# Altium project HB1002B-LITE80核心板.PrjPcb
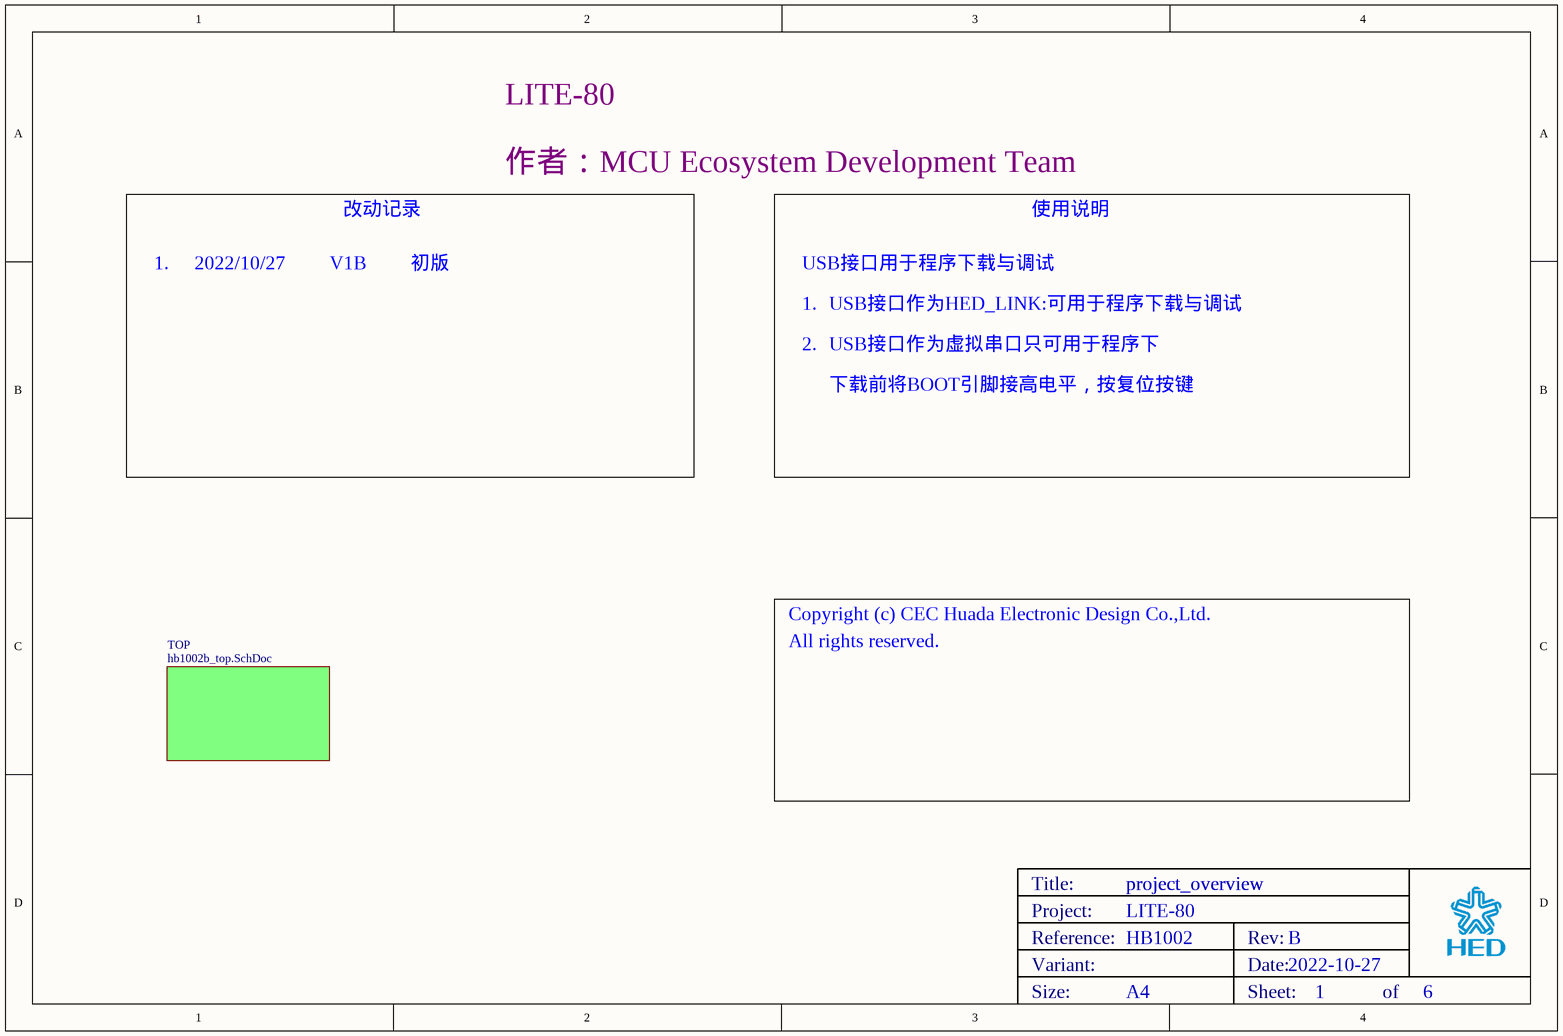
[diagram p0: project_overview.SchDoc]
Board_Assembly_Revision: 01; Board_Name: LITE-80; Board_PCB_Revision: B; Board_Reference: HB1002
6 sheets, 120 parts. Net scope: global (net labels, ports and power ports of the same name join across sheets).
Board file: hb1002b.PcbDoc
Sheets:
  project_overview.SchDoc
    TOP = hb1002b_top.SchDoc
      hed_link = hed_link.SchDoc
      arduino_extension_interfaces = arduino_extension_interfaces.SchDoc
      MCU = mcu.SchDoc
      power = power.SchDoc

## Sheet project_overview.SchDoc: project_overview
size A4; Date: 2022-10-27; DrawnBy: liuchao; SheetNumber: 1; SheetTotal: 6

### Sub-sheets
TOP = hb1002b_top.SchDoc: no entries

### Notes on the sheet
- 作者：MCU Ecosystem Development Team
- 改动记录
- 使用说明
- 1.
- 2022/10/27
- V1B
- 初版
- USB接口用于程序下载与调试
- USB接口作为HED_LINK:可用于程序下载与调试
- 2.
- USB接口作为虚拟串口只可用于程序下
- 下载前将BOOT引脚接高电平，按复位按键
- Copyright (c) CEC Huada Electronic Design Co.,Ltd.
- All rights reserved.

## Sheet hb1002b_top.SchDoc: top
size A4; Date: 2022-10-27; DrawnBy: liuchao; SheetNumber: 2; SheetTotal: 6
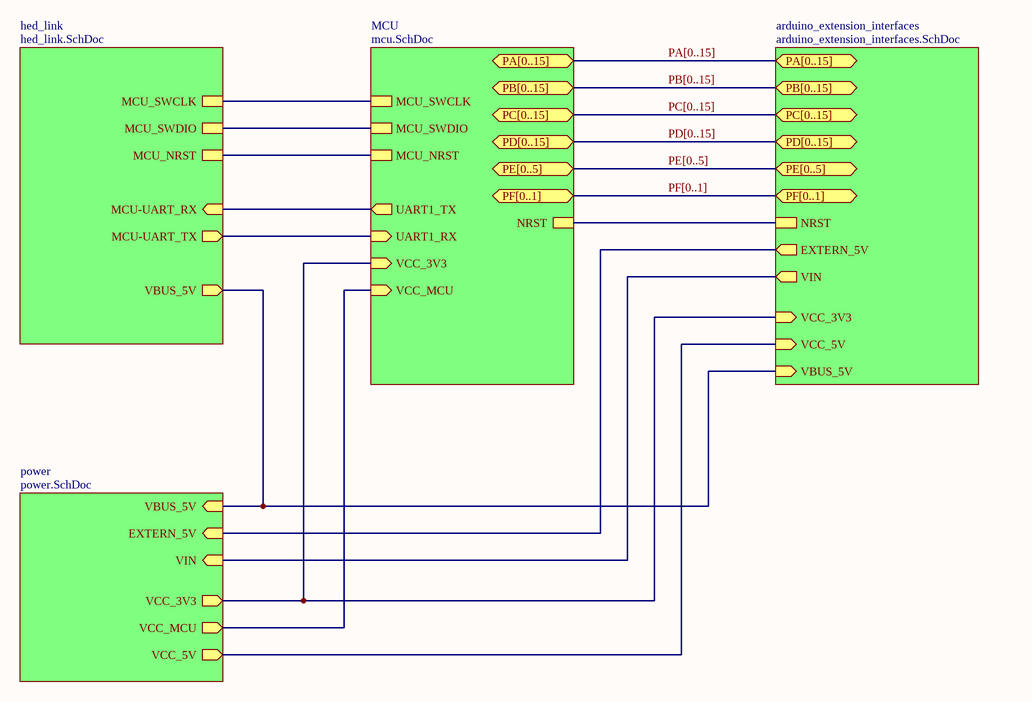
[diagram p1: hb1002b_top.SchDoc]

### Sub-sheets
arduino_extension_interfaces = arduino_extension_interfaces.SchDoc: NRST, VBUS_5V (in), EXTERN_5V (out), VIN (out), VCC_3V3 (in), VCC_5V (in)
hed_link = hed_link.SchDoc: MCU_SWDIO, MCU_SWCLK, MCU_NRST, MCU-UART_RX (in), MCU-UART_TX (out), VBUS_5V (out)
MCU = mcu.SchDoc: UART1_RX (in), UART1_TX (out), MCU_SWCLK, MCU_SWDIO, MCU_NRST, VCC_3V3 (in), VCC_MCU (in), NRST
power = power.SchDoc: VCC_MCU (out), VBUS_5V (in), EXTERN_5V (in), VIN (in), VCC_3V3 (out), VCC_5V (out)

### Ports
PA[0..15], PB[0..15], PC[0..15], PD[0..15], PE[0..5], PF[0..1]

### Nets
(unnamed): sheet hed_link/MCU_SWDIO, sheet MCU/MCU_SWDIO
(unnamed): sheet hed_link/MCU_SWCLK, sheet MCU/MCU_SWCLK  [a separate net that carries the same name]
(unnamed): sheet hed_link/MCU_NRST, sheet MCU/MCU_NRST  [a separate net that carries the same name]
(unnamed): sheet hed_link/MCU-UART_RX, sheet MCU/UART1_TX  [a separate net that carries the same name]
(unnamed): sheet hed_link/MCU-UART_TX, sheet MCU/UART1_RX  [a separate net that carries the same name]
(unnamed): sheet hed_link/VBUS_5V, sheet arduino_extension_interfaces/VBUS_5V, sheet power/VBUS_5V  [a separate net that carries the same name]
(unnamed): sheet arduino_extension_interfaces/NRST, sheet MCU/NRST  [a separate net that carries the same name]
(unnamed): sheet arduino_extension_interfaces/EXTERN_5V, sheet power/EXTERN_5V  [a separate net that carries the same name]
(unnamed): sheet arduino_extension_interfaces/VIN, sheet power/VIN  [a separate net that carries the same name]
(unnamed): sheet arduino_extension_interfaces/VCC_3V3, sheet MCU/VCC_3V3, sheet power/VCC_3V3  [a separate net that carries the same name]
(unnamed): sheet arduino_extension_interfaces/VCC_5V, sheet power/VCC_5V  [a separate net that carries the same name]
(unnamed): sheet MCU/VCC_MCU, sheet power/VCC_MCU  [a separate net that carries the same name]

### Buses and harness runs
bus PA[0..15] = port PA[0..15]
bus PB[0..15] = port PB[0..15]
bus PC[0..15] = port PC[0..15]
bus PD[0..15] = port PD[0..15]
bus PE[0..5] = port PE[0..5]
bus PF[0..1] = port PF[0..1]

## Sheet hed_link.SchDoc: HED_Link
size A4; Date: 2022-10-27; DrawnBy: liuchao; SheetNumber: 6; SheetTotal: 6
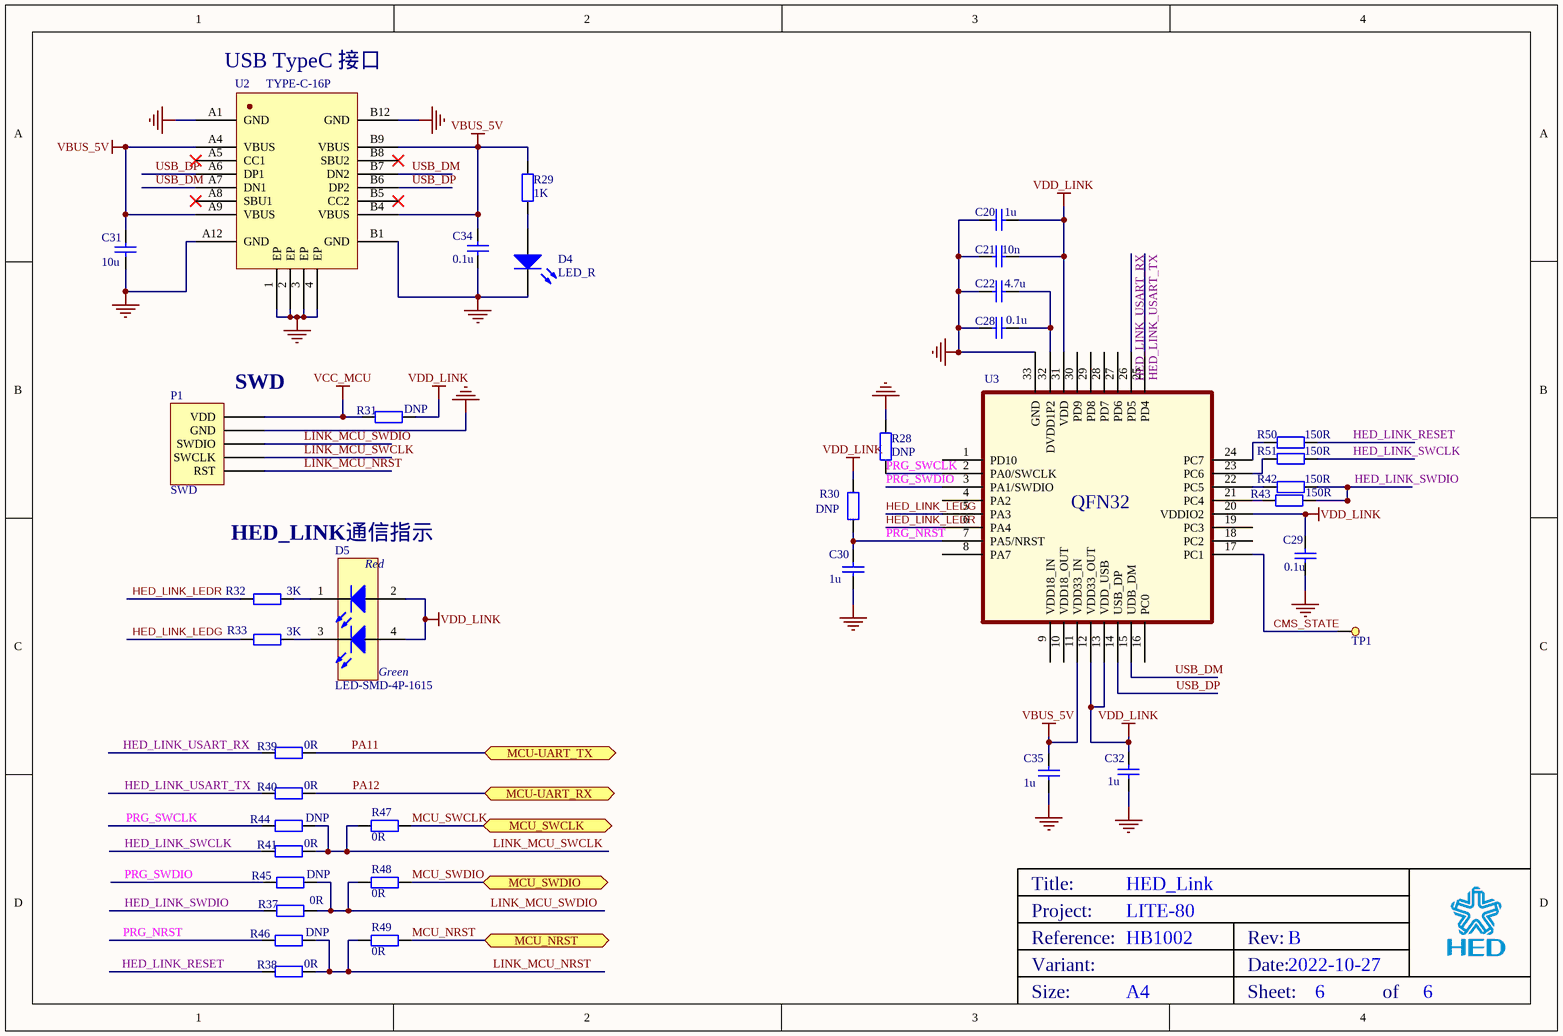
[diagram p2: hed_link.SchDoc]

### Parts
C20  1u  [0603]
C21  10n  [0603]
C22  4.7u  [0603]
C28  0.1u  [0603]
C29  0.1u  [0603]
C30  value 1u  [0603]  (hidden comment: 0.1u)
C31  10u  [0603]
C32  1u  [0603]
C34  0.1u  [0603]
C35  1u  [0603]
D4  LED_R  [0603 - p]
D5  Manufacturer_Part_Number: LED-SMD-4P-1615  [LED-SMD_4P_1615]  (hidden comment: LD_BICOLOR_CMS)
P1  SWD  [HED_5_4_2.5]
R28  DNP  [0603]
R29  1K  [0603]
R30  DNP  [0603]
R31  DNP  [0603]
R32  3K  [0603]
R33  3K  [0603]
R37  0R  [0603]
R38  0R  [0603]
R39  0R  [0603]
R40  0R  [0603]
R41  0R  [0603]
R42  150R  [0603]
R43  150R  [0603]
R44  DNP  [0603]
R45  DNP  [0603]
R46  DNP  [0603]
R47  0R  [0603]
R48  0R  [0603]
R49  0R  [0603]
R50  150R  [0603]
R51  150R  [0603]
TP1  TEST_POINT  [TEST_POINT]  (value not drawn)
U2  TYPE-C-16P  [HED-KH-TYPE-C-16P]
U3  MCU  [HED-QFN-32_5x5x05P]  (value not drawn)

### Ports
MCU-UART_RX (bidir), MCU-UART_TX (bidir), MCU_NRST, MCU_SWCLK, MCU_SWDIO

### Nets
GND: C20.1 C21.1 C22.1 C28.1 C29.2 C30.2 C31.1 C32.2 C34.1 C35.2 D4.2(K) P1.2(GND) R28.1 U2.1(EP) U2.2(EP) U2.3(EP) U2.4(EP) U2.A1(GND) U2.A12(GND) U2.B1(GND) U2.B12(GND) U3.33(GND)
VBUS_5V: C31.2 C34.2 C35.1 R29.1 U2.A4(VBUS) U2.A9(VBUS) U2.B4(VBUS) U2.B9(VBUS) U3.11(VDD33_IN)
VCC_MCU: P1.1(VDD) R31.1
VDD_LINK: C20.2 C21.2 C29.1 C32.1 D5.2(RED_cathode) D5.4(YellowGreen_anode) R30.1 R31.2 U3.12(VDD33_OUT) U3.13(VDD_USB) U3.20(VDDIO2) U3.31(VDD)
CMS_STATE: TP1.1 U3.17(PC1)
HED_LINK_LEDG: R33.1 U3.5(PA3)
HED_LINK_LEDR: R32.1 U3.6(PA4)
HED_LINK_RESET: R38.1 R50.2
HED_LINK_SWCLK: R41.1 R51.2
HED_LINK_SWDIO: R37.1 R42.2 R43.2
HED_LINK_USART_RX: R39.1 U3.26(PD5)
HED_LINK_USART_TX: R40.1 U3.25(PD4)
LINK_MCU_NRST: P1.5(RST) R38.2 R46.2 R49.2
LINK_MCU_SWCLK: P1.4(SWCLK) R41.2 R44.2 R47.2
LINK_MCU_SWDIO: P1.3(SWDIO) R37.2 R45.2 R48.2
MCU_NRST: R49.1 ; port MCU_NRST
MCU_SWCLK: R47.1 ; port MCU_SWCLK
MCU_SWDIO: R48.1 ; port MCU_SWDIO
PA11: R39.2 ; port MCU-UART_TX
PA12: R40.2 ; port MCU-UART_RX
PRG_NRST: C30.1 R30.2 R46.1 U3.7(PA5/NRST)
PRG_SWCLK: R28.2 R44.1 U3.2(PA0/SWCLK)
PRG_SWDIO: R45.1 U3.3(PA1/SWDIO)
USB_DM: U2.A7(DN1) U2.B7(DN2) U3.15(UDB_DM)
USB_DP: U2.A6(DP1) U2.B6(DP2) U3.14(USB_DP)
NetC22_2: C22.2 C28.2 U3.32(DVDD1P2)
NetD4_1: D4.1(A) R29.2
NetD5_1: D5.1(Red_anode) R32.2
NetD5_3: D5.3(YellowGreen_cathode) R33.2
NetR42_1: R42.1 U3.22(PC5)
NetR43_1: R43.1 U3.21(PC4)
NetR50_1: R50.1 U3.24(PC7)
NetR51_1: R51.1 U3.23(PC6)

Not connected (* = marked no-connect by the designer): U2 A5(CC1)* A8(SBU1)* B5(CC2)* B8(SBU2)*; U3 1(PD10) 4(PA2) 8(PA7) 9(VDD18_IN) 10(VDD18_OUT) 16(PC0) 18(PC2) 19(PC3) 27(PD6) 28(PD7) 29(PD8) 30(PD9)

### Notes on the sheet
- (near U2) USB TypeC 接口
- (near P1) SWD
- HED_LINK通信指示

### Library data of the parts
C20-C22 C28-C30 C32 C35 = MCD-00211: Capacitor, MLCC, 100nF, 16V, X7R, 10%, 0603, T=0,8mm; Manufacturer_Part_Number: CC0603KRX7R7BB104; Manufacturer: YAGEO; Provided_By: Subcon; Initial_Board_Reference: mb1319
C31 = 0603 4.7uF 10% 16V: 贴片电容
C34 = 0603 100nF 10% 50V: 贴片电容
D4 = LED3: Typical BLUE SiC LED; sold/unsold: sold
D5 = LD_BICOLOR_CMS: LED Bicolor; Internal_Part_Number: MCD-00051; Part_Type: Display; Manufacturer: AVAGO TECHNOLOGIES; Alternate_Manufacturer_Part_Number: LE-RGW35280; Alternate_Manufacturer: EVERLUCK; ECCN_US: EAR99; ECCN_EU: NEC; Provided_By: Subcon; Initial_Board_Reference: mb1274
R28 R42-R51 = Res: 贴片电阻; Value: 1K
R29 = Res2: 贴片电阻
R30-R33 R37-R41 = Res2: 贴片电阻; Value: 1K
U2 = KH-TYPE-C-16P: TYPE-C USB接口
U3 = CIU98-H

## Sheet arduino_extension_interfaces.SchDoc: arduino interface
size A4; Date: 2022-10-27; DrawnBy: liuchao; SheetNumber: 5; SheetTotal: 6
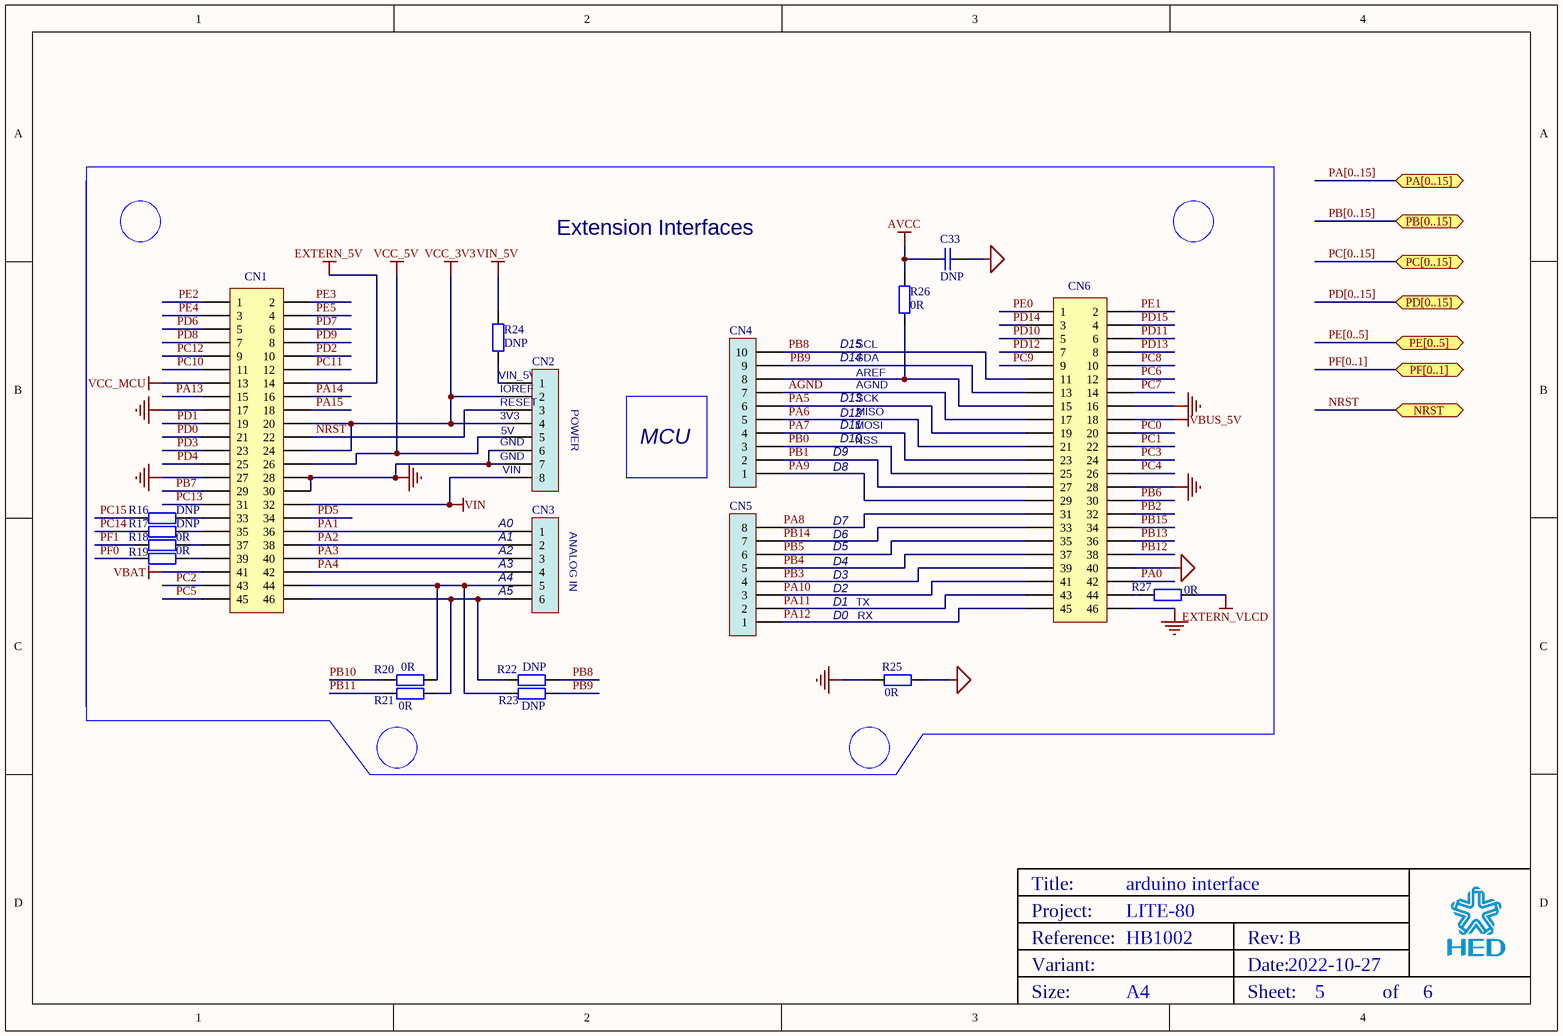
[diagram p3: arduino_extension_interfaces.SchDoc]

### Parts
C33  DNP  [0603]
CN1  Header 23x2  [HEADER_1X23_2.54]  (value not drawn)
CN2  Socket 8x1  [HEADER_1X8_2.54]  (value not drawn)
CN3  Socket 6x1  [HEADER_1X6-2.54]  (value not drawn)
CN4  Socket 10x1  [HEADER_1X10_2.54]  (value not drawn)
CN5  Socket 8x1  [HEADER_1X8_2.54]  (value not drawn)
CN6  Header 23x2  [HEADER_1X23_2.54]  (value not drawn)
R16  DNP  [0603]
R17  DNP  [0603]
R18  0R  [0603]
R19  0R  [0603]
R20  0R  [0603]
R21  0R  [0603]
R22  DNP  [0603]
R23  DNP  [0603]
R24  DNP  [0603]
R25  0R  [0603]
R26  0R  [0603]
R27  0R  [0603]

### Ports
NRST, PA[0..15] (bidir), PB[0..15] (bidir), PC[0..15] (bidir), PD[0..15], PE[0..5], PF[0..1] (bidir)

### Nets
AGND: C33.1 CN4.7 CN6.17 CN6.40 R25.1
EXTERN_5V: CN1.14
EXTERN_VLCD: R27.1
GND: CN1.17 CN1.27 CN1.28 CN1.30 CN2.6 CN2.7 CN6.16 CN6.28 CN6.46 R25.2
PA0: C33.2 CN6.42 R26.1  [also labelled AVCC]
VBAT: CN1.41
VBUS_5V: CN6.18
VCC_3V3: CN1.20 CN1.24 CN2.2 CN2.4
VCC_5V: CN1.26 CN2.5
VCC_MCU: CN1.13
VIN: CN1.32 CN2.8
VIN_5V: R24.1
NRST: CN1.22 CN2.3 ; port NRST
PA1: CN1.36 CN3.1
PA2: CN1.38 CN3.2
PA3: CN1.40 CN3.3
PA4: CN1.42 CN3.4
PA5: CN4.6 CN6.19
PA6: CN4.5 CN6.21
PA7: CN4.4 CN6.23
PA8: CN5.8 CN6.31
PA9: CN4.1 CN6.29
PA10: CN5.3 CN6.41
PA11: CN5.2 CN6.43
PA12: CN5.1 CN6.45
PA13: CN1.15
PA14: CN1.16
PA15: CN1.18
PB0: CN4.3 CN6.25
PB1: CN4.2 CN6.27
PB2: CN6.32
PB3: CN5.4 CN6.39
PB4: CN5.5 CN6.37
PB5: CN5.6 CN6.35
PB6: CN6.30
PB7: CN1.29
PB8: CN4.10 CN6.11 R22.1
PB9: CN4.9 CN6.13 R23.1
PB10: R20.2
PB11: R21.2
PB12: CN6.38
PB13: CN6.36
PB14: CN5.7 CN6.33
PB15: CN6.34
PC0: CN6.20
PC1: CN6.22
PC2: CN1.43
PC3: CN6.24
PC4: CN6.26
PC5: CN1.45
PC6: CN6.12
PC7: CN6.14
PC8: CN6.10
PC9: CN6.9
PC10: CN1.11
PC11: CN1.12
PC12: CN1.9
PC13: CN1.31
PC14: R17.2
PC15: R16.2
PD0: CN1.21
PD1: CN1.19
PD2: CN1.10
PD3: CN1.23
PD4: CN1.25
PD5: CN1.34
PD6: CN1.5
PD7: CN1.6
PD8: CN1.7
PD9: CN1.8
PD10: CN6.5
PD11: CN6.6
PD12: CN6.7
PD13: CN6.8
PD14: CN6.3
PD15: CN6.4
PE0: CN6.1
PE1: CN6.2
PE2: CN1.1
PE3: CN1.2
PE4: CN1.3
PE5: CN1.4
PF0: R19.2
PF1: R18.2
NetCN1_33: CN1.33 R16.1
NetCN1_35: CN1.35 R17.1
NetCN1_37: CN1.37 R18.1
NetCN1_39: CN1.39 R19.1
NetCN1_44: CN1.44 CN3.5 R20.1 R23.2
NetCN1_46: CN1.46 CN3.6 R21.1 R22.2
NetCN2_1: CN2.1 R24.2
NetCN4_8: CN4.8 CN6.15 R26.2
NetCN6_44: CN6.44 R27.2

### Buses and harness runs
bus PA[0..15] = port PA[0..15]
bus PB[0..15] = port PB[0..15]
bus PC[0..15] = port PC[0..15]
bus PD[0..15] = port PD[0..15]
bus PE[0..5] = port PE[0..5]
bus PF[0..1] = port PF[0..1]

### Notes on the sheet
- Extension Interfaces
- (near CN2) VIN_5V
- D14
- D15
- (near R26) SDA
- (near R26) SCL
- AREF
- (near CN2) IOREF
- (near CN2) 3V3
- (near CN2) GND
- (near CN2) RESET
- (near CN2) 5V
- (near CN2) POWER
- MCU
- D10
- D13
- D12
- D11
- MOSI
- NSS
- AGND
- MISO
- SCK
- (near CN2) VIN
- D8
- D9
- (near CN3) A0
- (near CN3) A1
- (near CN3) A2
- (near CN3) A3
- (near CN3) A4
- (near CN3) ANALOG IN
- D4
- D3
- D5
- D6
- D7
- (near CN3) A5
- D0
- D1
- D2
- TX
- RX

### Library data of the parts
C33 = MCD-00211: as C20 on sheet hed_link
CN1 CN6 = Header 23x2: Header, 19x2, 2,54mm, VR, TH, Height 5.84mm/10.16mm; Internal_Part_Number: MCD-00213; Manufacturer: SAMTEC; Part_Type: Connector; Manufacturer_Part_Number: TSW-119-09-x-D1; Value: Header 19x2; Provided_By: Subcon; Initial_Board_Reference: mb1319
CN2 = MCD-00261: Socket, 8x1, 2.54mm, VR, TH, Height 8.51mm/10mm; Manufacturer_Part_Number: SSW-108-03-x-S; Manufacturer: SAMTEC; Part_Type: Connector; Provided_By: Subcon; Initial_Board_Reference: mb1319
CN3 = MCD-00260: Socket, 6x1, 2.54mm, VR, TH, Height 8.51mm/10mm; Part_Type: Connector; Manufacturer_Part_Number: SSW-106-03-x-S; Manufacturer: SAMTEC; Provided_By: Subcon; Initial_Board_Reference: mb1319
CN4 = MCD-00262: Socket, 10x1, 2.54mm, VR, TH, Height 8.51mm/10mm; Manufacturer_Part_Number: SSW-110-03-x-S; Manufacturer: SAMTEC; Part_Type: Connector; Provided_By: Subcon; Initial_Board_Reference: mb1319
CN5 = MCD-00261: Socket, 8x1, 2.54mm, VR, TH, Height 8.51mm/10mm; Part_Type: Connector; Manufacturer_Part_Number: SSW-108-03-x-S; Manufacturer: SAMTEC; Provided_By: Subcon; Initial_Board_Reference: mb1319
R16-R27 = Res2: 贴片电阻; Value: 1K

## Sheet mcu.SchDoc: MCU
size A4; Date: 2022-10-27; DrawnBy: liuchao; SheetNumber: 3; SheetTotal: 6
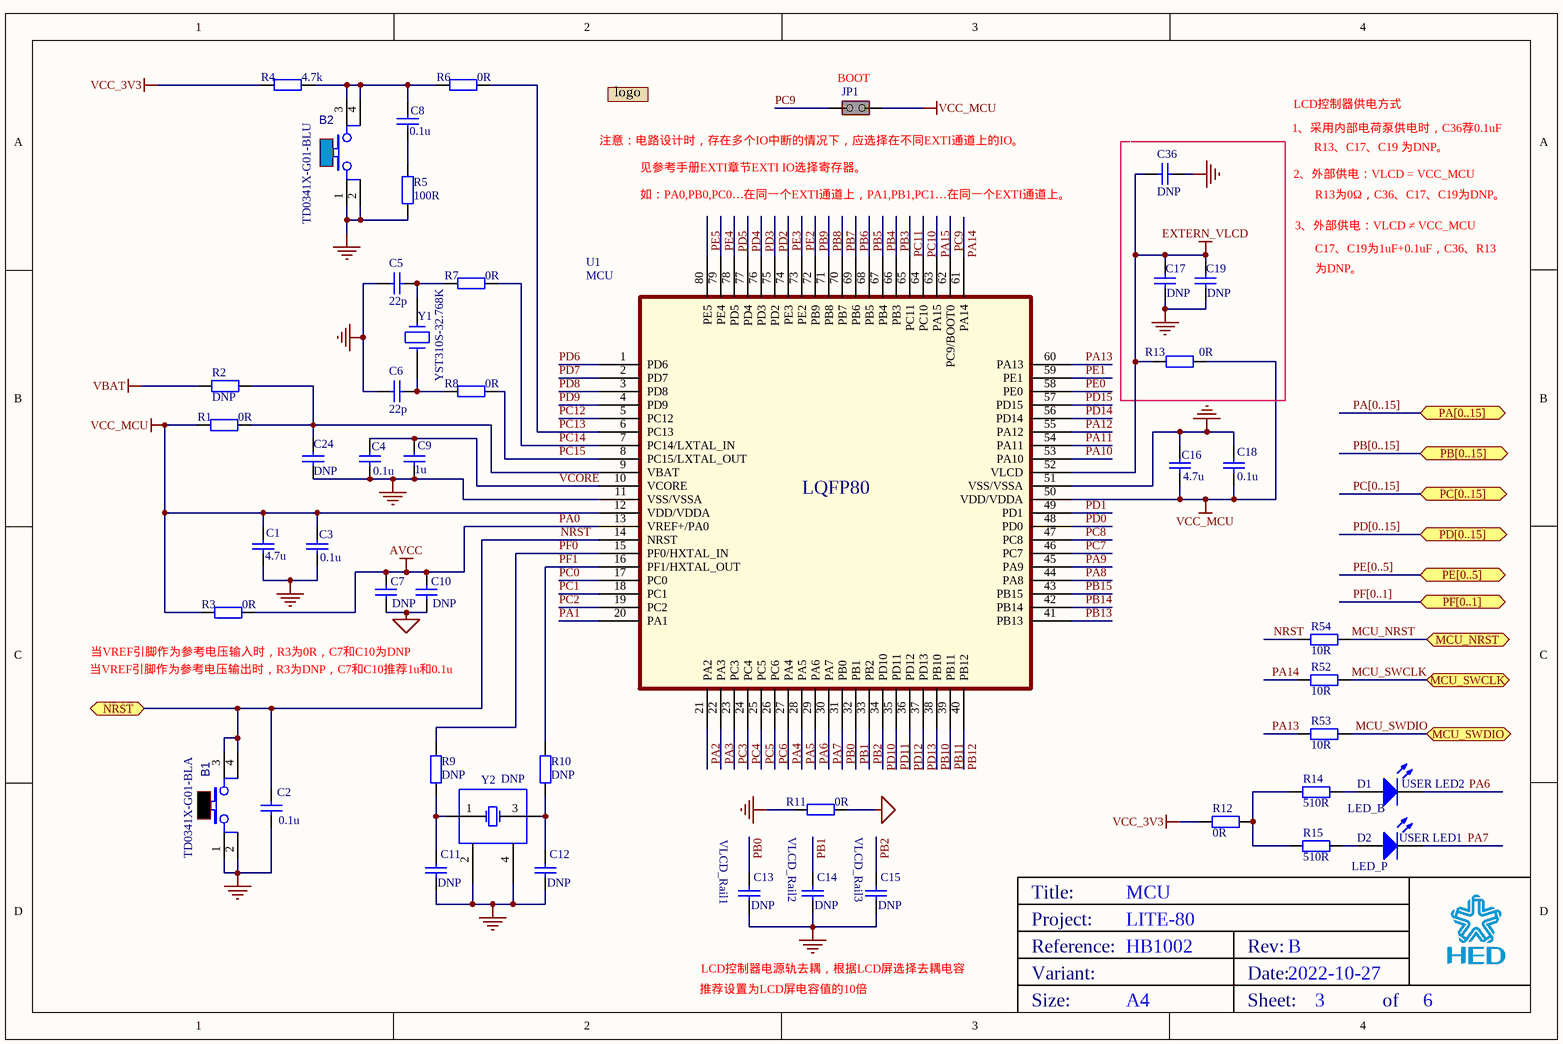
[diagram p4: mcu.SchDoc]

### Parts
B1  Manufacturer_Part_Number: TD0341X-G01-BLA  [SWI_WEALTHMETAL_TD-0341_4P_BLACK]  (hidden comment: SW-PUSH-CMS_BLACK)
B2  Manufacturer_Part_Number: TD0341X-G01-BLU  [SWI_WEALTHMETAL_TD-0341_4P_BLUE]  (hidden comment: SW-PUSH-CMS_BLUE)
C1  4.7u  [0603]
C2  0.1u  [0603]
C3  0.1u  [0603]
C4  0.1u  [0603]
C5  22p  [0603]
C6  22p  [0603]
C7  DNP  [0603]
C8  0.1u  [0603]
C9  1u  [0603]
C10  DNP  [0603]
C11  DNP  [0603]
C12  DNP  [0603]
C13  DNP  [0603]
C14  DNP  [0603]
C15  DNP  [0603]
C16  4.7u  [0603]
C17  DNP  [0603]
C18  0.1u  [0603]
C19  DNP  [0603]
C24  DNP  [0603]
C36  DNP  [0603]
D1  LED_B  [0603 - p]
D2  LED_P  [0603 - p]
JP1  Shunt Fitted  [HEADER_1X2_2.54]  (value not drawn)
logo1  logo  [华大电子LOGO]  (value not drawn)
R1  0R  [0603]
R2  DNP  [0603]
R3  0R  [0603]
R4  4.7k  [0603]
R5  100R  [0603]
R6  0R  [0603]
R7  0R  [0603]
R8  0R  [0603]
R9  DNP  [0603]
R10  DNP  [0603]
R11  0R  [0603]
R12  0R  [0603]
R13  0R  [0603]
R14  510R  [0603]
R15  510R  [0603]
R52  10R  [0603]
R53  10R  [0603]
R54  10R  [0603]
U1  MCU  [LQFP-80N-12X12]
Y1  value YST310S-32.768K  [CRY_3215SA_2P]  (hidden comment: YST310S)
Y2  DNP  [3.2*2.5*0.7 OSC]

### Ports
MCU_NRST, MCU_SWCLK, MCU_SWDIO, NRST, PA[0..15] (bidir), PB[0..15] (bidir), PC[0..15] (bidir), PD[0..15], PE[0..5], PF[0..1] (bidir)

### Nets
AGND: C7.1 C10.1 R11.1
EXTERN_VLCD: C17.1 C19.1 C36.1 R13.1 U1.52(VLCD)
GND: B1.1 B1.2 B2.1 B2.2 C1.1 C2.2 C3.1 C4.2 C5.1 C6.1 C9.2 C11.2 C12.2 C13.2 C14.2 C15.2 C16.2 C17.2 C18.2 C19.2 C24.1 C36.2 R5.2 R11.2 U1.11(VSS/VSSA) U1.51(VSS/VSSA) Y2.2(OSC2) Y2.4(OSC4)
PA0: C7.2 C10.2 R3.1 U1.13(VREF+/PA0)  [also labelled AVCC]
VBAT: R2.1
VCC_3V3: R4.2 R12.2
VCC_MCU: C1.2 C3.2 C16.1 C18.1 JP1.2(NO) R1.2 R3.2 R13.2 U1.12(VDD/VDDA) U1.50(VDD/VDDA)
MCU_NRST: R54.1 ; port MCU_NRST
MCU_SWCLK: R52.1 ; port MCU_SWCLK
MCU_SWDIO: R53.1 ; port MCU_SWDIO
NRST: B1.3 B1.4 C2.1 R54.2 U1.14(NRST) ; port NRST
PA1: U1.20(PA1)
PA2: U1.21(PA2)
PA3: U1.22(PA3)
PA4: U1.27(PA4)
PA5: U1.28(PA5)
PA6: D1.2(K) U1.29(PA6)
PA7: D2.2(K) U1.30(PA7)
PA8: U1.44(PA8)
PA9: U1.45(PA9)
PA10: U1.53(PA10)
PA11: U1.54(PA11)
PA12: U1.55(PA12)
PA13: R53.2 U1.60(PA13)
PA14: R52.2 U1.61(PA14)
PA15: U1.63(PA15)
PB0: C13.1 U1.31(PB0)
PB1: C14.1 U1.32(PB1)
PB2: C15.1 U1.33(PB2)
PB3: U1.66(PB3)
PB4: U1.67(PB4)
PB5: U1.68(PB5)
PB6: U1.69(PB6)
PB7: U1.70(PB7)
PB8: U1.71(PB8)
PB9: U1.72(PB9)
PB10: U1.38(PB10)
PB11: U1.39(PB11)
PB12: U1.40(PB12)
PB13: U1.41(PB13)
PB14: U1.42(PB14)
PB15: U1.43(PB15)
PC0: U1.17(PC0)
PC1: U1.18(PC1)
PC2: U1.19(PC2)
PC3: U1.23(PC3)
PC4: U1.24(PC4)
PC5: U1.25(PC5)
PC6: U1.26(PC6)
PC7: U1.46(PC7)
PC8: U1.47(PC8)
PC9: JP1.1(COMMON) U1.62(PC9/BOOT0)
PC10: U1.64(PC10)
PC11: U1.65(PC11)
PC12: U1.5(PC12)
PC13: R6.1 U1.6(PC13)
PC14: R7.1 U1.7(PC14/LXTAL_IN)
PC15: R8.1 U1.8(PC15/LXTAL_OUT)
PD0: U1.48(PD0)
PD1: U1.49(PD1)
PD2: U1.75(PD2)
PD3: U1.76(PD3)
PD4: U1.77(PD4)
PD5: U1.78(PD5)
PD6: U1.1(PD6)
PD7: U1.2(PD7)
PD8: U1.3(PD8)
PD9: U1.4(PD9)
PD10: U1.34(PD10)
PD11: U1.35(PD11)
PD12: U1.36(PD12)
PD13: U1.37(PD13)
PD14: U1.56(PD14)
PD15: U1.57(PD15)
PE0: U1.58(PE0)
PE1: U1.59(PE1)
PE2: U1.73(PE2)
PE3: U1.74(PE3)
PE4: U1.79(PE4)
PE5: U1.80(PE5)
PF0: R9.2 U1.15(PF0/HXTAL_IN)
PF1: R10.2 U1.16(PF1/HXTAL_OUT)
VCORE: C4.1 C9.1 U1.10(VCORE)
NetB2_3: B2.3 B2.4 C8.2 R4.1 R6.2
NetC5_2: C5.2 R7.2 Y1.1
NetC6_2: C6.2 R8.2 Y1.2
NetC8_1: C8.1 R5.1
NetC11_1: C11.1 R9.1 Y2.1(OSC1)
NetC12_1: C12.1 R10.1 Y2.3(OSC3)
NetC24_2: C24.2 R1.1 R2.2 U1.9(VBAT)
NetD1_1: D1.1(A) R14.1
NetD2_1: D2.1(A) R15.1
NetR12_1: R12.1 R14.2 R15.2

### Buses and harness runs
bus PA[0..15] = port PA[0..15]
bus PB[0..15] = port PB[0..15]
bus PC[0..15] = port PC[0..15]
bus PD[0..15] = port PD[0..15]
bus PE[0..5] = port PE[0..5]
bus PF[0..1] = port PF[0..1]

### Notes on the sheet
- (near JP1) BOOT
- LCD控制器供电方式
- 注意：电路设计时，存在多个IO中断的情况下，应选择在不同EXTI通道上的IO。
- 见参考手册EXTI章节EXTI IO选择寄存器。
- 1、采用内部电荷泵供电时，C36荐0.1uF
- 2、外部供电：VLCD = VCC_MCU
- R13、C17、C19 为DNP。
- 如：PA0,PB0,PC0…在同一个EXTI通道上，PA1,PB1,PC1…在同一个EXTI通道上。
- 3、外部供电：VLCD ≠ VCC_MCU
- C17、C19为1uF+0.1uF，C36、R13
- R13为0Ω，C36、C17、C19为DNP。
- 为DNP。
- (near R3) 当VREF引脚作为参考电压输入时，R3为0R，C7和C10为DNP
- (near R3) 当VREF引脚作为参考电压输出时，R3为DNP，C7和C10推荐1u和0.1u
- (near D1) USER LED2
- (near C13) VLCD_Rail1
- (near C14) VLCD_Rail2
- (near C15) VLCD_Rail3
- (near D2) USER LED1
- 推荐设置为LCD屏电容值的10倍
- LCD控制器电源轨去耦，根据LCD屏选择去耦电容

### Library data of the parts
B1 = MCD-00001: Non-Open Push-Button 0.1A 24V; Part_Type: Misc; Manufacturer: WEALTHMETAL; Value: SW_BLACK; Provided_By: Subcon; Initial_Board_Reference: mb1274
B2 = MCD-00002: Non-Open Push-Button 0.1A 24V; Part_Type: Misc; Manufacturer: WEALTHMETAL; Value: SW_BLUE; Provided_By: Subcon; Initial_Board_Reference: mb1274
C1 C13-C17 C19 C36 = MCD-00009: Capacitor, MLCC, 4.7uF, 16V, X5R, 10%, 0603, T=0.8mm; Manufacturer_Part_Number: CC0603KRX5R7BB475; Manufacturer: YAGEO; Provided_By: subcon; Initial_Board_Reference: mb1274
C2-C4 C7 C9 C10 C18 = MCD-00211: as C20 on sheet hed_link
C5 C6 = MCD-00666: Capacitor,5.6pF,0.1pF,16V,NPO,0603; Manufacturer_Part_Number: CC0603BRNPO7BN5R6; Manufacturer: YAGEO; Provided_By: Subcon; Initial_Board_Reference: MB1360
C8 = MCD-00211: 贴片电容; Manufacturer_Part_Number: CC0603KRX7R7BB104; Manufacturer: YAGEO; Provided_By: Subcon; Initial_Board_Reference: mb1319
C11 C12 = MCD-00009: 贴片电容33p; Manufacturer_Part_Number: CC0603KRX5R7BB475; Manufacturer: YAGEO; Provided_By: subcon; Initial_Board_Reference: mb1274
C24 = MCD-00014: Capacitor, MLCC, 10uF, 25V, X5R, 10%, 0805, T=0,85mm; Manufacturer_Part_Number: CC0805KRX5R8BB106; Manufacturer: YAGEO; Provided_By: Subcon; Initial_Board_Reference: mb1274
D1 D2 = LED1: Typical RED GaAs LED
JP1 = MCD-00683: Header, 2x1, 2,54mm, VR, TH, Height 5.84mm/2.54mm - Shunt Fitted by default; Part_Type: Connector; Manufacturer_Part_Number: TSW-102-07-x-S; Manufacturer: SAMTEC; Provided_By: Subcon; Initial_Board_Reference: MB1331
R1-R15 = Res2: 贴片电阻; Value: 1K
R52-R54 = Res: 贴片电阻; Value: 1K
U1 = LQFP80
Y1 = MCD-00091: 32.768k无源晶振; Part_Type: Crystal_Osc; Manufacturer_Part_Number: NX3215SA 32.768KHz EXS00A-MU00525; Manufacturer: NDK; ECCN_US: EAR99; ECCN_EU: NEC; Provided_By: STM; Initial_Board_Reference: mb1274
Y2 = XTAL_4: 'X32258MSB4SI 无源晶振

## Sheet power.SchDoc: power
size A4; Date: 2022-10-27; DrawnBy: liuchao; SheetNumber: 4; SheetTotal: 6
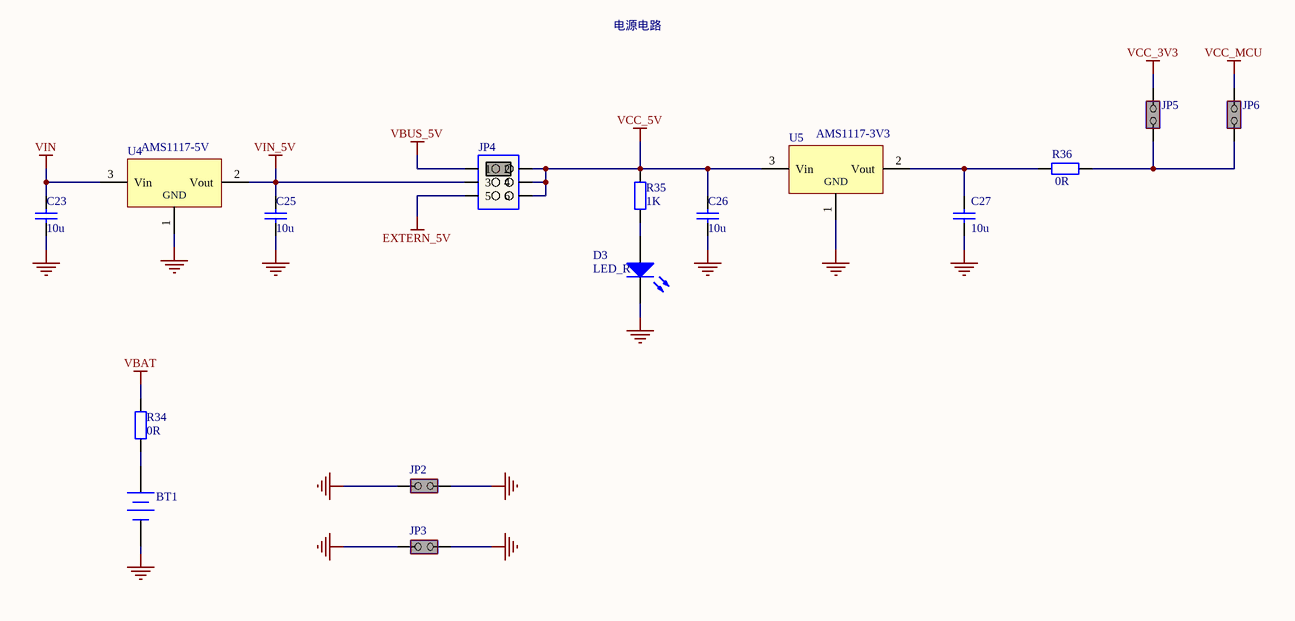
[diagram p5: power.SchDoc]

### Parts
BT1  (no value)  [CR1220]
C23  10u  [0603]
C25  10u  [0603]
C26  10u  [0603]
C27  10u  [0603]
D3  LED_R  [0603 - P]
JP2  Shunt Fitted  [CON_SAMTEC_TSW-102-07-G-S]  (value not drawn)
JP3  Shunt Fitted  [CON_SAMTEC_TSW-102-07-G-S]  (value not drawn)
JP4  Shunt Fitted 1-2  [HEADER_2X3_2.54]  (value not drawn)
JP5  Shunt Fitted  [HEADER_1X2_2.54]  (value not drawn)
JP6  Shunt Fitted  [HEADER_1X2_2.54]  (value not drawn)
R34  0R  [0603]
R35  1K  [0603]
R36  0R  [0603]
U4  AMS1117-5V  [SOT223]
U5  AMS1117-3V3  [SOT223]

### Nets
EXTERN_5V: JP4.5
GND: BT1.2(-) C23.1 C25.1 C26.1 C27.1 D3.2(K) JP2.1(COMMON) JP2.2(NO) JP3.1(COMMON) JP3.2(NO) U4.1(GND) U5.1(GND)
VBAT: R34.1
VBUS_5V: JP4.1
VCC_3V3: JP5.1(COMMON)
VCC_5V: C26.2 JP4.2 JP4.4 JP4.6 R35.2 U5.3(Vin)
VCC_MCU: JP6.1(COMMON)
VIN: C23.2 U4.3(Vin)
VIN_5V: C25.2 JP4.3 U4.2(Vout)
NetBT1_1: BT1.1(+) R34.2
NetC27_2: C27.2 R36.2 U5.2(Vout)
NetD3_1: D3.1(A) R35.1
NetJP5_2: JP5.2(NO) JP6.2(NO) R36.1

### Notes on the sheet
- 电源电路

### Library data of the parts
BT1 = Battery: Multicell Battery
C23 C25-C27 = MCD-00014: as C24 on sheet mcu
D3 = LED1: Typical RED GaAs LED
JP2 JP3 JP5 JP6 = MCD-00683: as JP1 on sheet mcu
JP4 = Jumper_Header 4x2 Fitted 1-2: Header, 4x2, 2,54mm, VR, TH, Height 5.84mm/2.54mm - Shunt Fitted 1-2; Internal_Part_Number: MCD-00686; Part_Type: Connector; Manufacturer_Part_Number: TSW-104-07-x-D; Manufacturer: SAMTEC; Provided_By: Subcon; Initial_Board_Reference: MB1331
R34 R36 = Res2: 贴片电阻; Value: 1K
R35 = Res2: 贴片电阻
U4 U5 = AMS1117: IC REG LDO 5V 0.8A SOT223; Internal_Part_Number: MCD-00088; Manufacturer_Part_Number: LD1117S50TR; Manufacturer: STMICROELECTRONICS; ECCN_US: EAR99; ECCN_EU: NEC; Provided_By: Subcon; Initial_Board_Reference: mb1274

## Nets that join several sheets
AGND: arduino_extension_interfaces (5 pins), mcu (C7.1 C10.1 R11.1)
EXTERN_5V: arduino_extension_interfaces (CN1.14), power (JP4.5)
EXTERN_VLCD: arduino_extension_interfaces (R27.1), mcu (5 pins)
GND: hed_link (22 pins), arduino_extension_interfaces (10 pins), mcu (28 pins), power (12 pins)
PA0: arduino_extension_interfaces (C33.2 CN6.42 R26.1), mcu (C7.2 C10.2 R3.1 U1.13)
VBAT: arduino_extension_interfaces (CN1.41), mcu (R2.1), power (R34.1)
VBUS_5V: hed_link (9 pins), arduino_extension_interfaces (CN6.18), power (JP4.1)
VCC_3V3: arduino_extension_interfaces (CN1.20 CN1.24 CN2.2 CN2.4), mcu (R4.2 R12.2), power (JP5.1)
VCC_5V: arduino_extension_interfaces (CN1.26 CN2.5), power (6 pins)
VCC_MCU: hed_link (P1.1 R31.1), arduino_extension_interfaces (CN1.13), mcu (10 pins), power (JP6.1)
VIN: arduino_extension_interfaces (CN1.32 CN2.8), power (C23.2 U4.3)
VIN_5V: arduino_extension_interfaces (R24.1), power (C25.2 JP4.3 U4.2)
MCU_NRST: hed_link (R49.1), mcu (R54.1)
MCU_SWCLK: hed_link (R47.1), mcu (R52.1)
MCU_SWDIO: hed_link (R48.1), mcu (R53.1)
NRST: arduino_extension_interfaces (CN1.22 CN2.3), mcu (5 pins)
PA1: arduino_extension_interfaces (CN1.36 CN3.1), mcu (U1.20)
PA2: arduino_extension_interfaces (CN1.38 CN3.2), mcu (U1.21)
PA3: arduino_extension_interfaces (CN1.40 CN3.3), mcu (U1.22)
PA4: arduino_extension_interfaces (CN1.42 CN3.4), mcu (U1.27)
PA5: arduino_extension_interfaces (CN4.6 CN6.19), mcu (U1.28)
PA6: arduino_extension_interfaces (CN4.5 CN6.21), mcu (D1.2 U1.29)
PA7: arduino_extension_interfaces (CN4.4 CN6.23), mcu (D2.2 U1.30)
PA8: arduino_extension_interfaces (CN5.8 CN6.31), mcu (U1.44)
PA9: arduino_extension_interfaces (CN4.1 CN6.29), mcu (U1.45)
PA10: arduino_extension_interfaces (CN5.3 CN6.41), mcu (U1.53)
PA11: hed_link (R39.2), arduino_extension_interfaces (CN5.2 CN6.43), mcu (U1.54)
PA12: hed_link (R40.2), arduino_extension_interfaces (CN5.1 CN6.45), mcu (U1.55)
PA13: arduino_extension_interfaces (CN1.15), mcu (R53.2 U1.60)
PA14: arduino_extension_interfaces (CN1.16), mcu (R52.2 U1.61)
PA15: arduino_extension_interfaces (CN1.18), mcu (U1.63)
PB0: arduino_extension_interfaces (CN4.3 CN6.25), mcu (C13.1 U1.31)
PB1: arduino_extension_interfaces (CN4.2 CN6.27), mcu (C14.1 U1.32)
PB2: arduino_extension_interfaces (CN6.32), mcu (C15.1 U1.33)
PB3: arduino_extension_interfaces (CN5.4 CN6.39), mcu (U1.66)
PB4: arduino_extension_interfaces (CN5.5 CN6.37), mcu (U1.67)
PB5: arduino_extension_interfaces (CN5.6 CN6.35), mcu (U1.68)
PB6: arduino_extension_interfaces (CN6.30), mcu (U1.69)
PB7: arduino_extension_interfaces (CN1.29), mcu (U1.70)
PB8: arduino_extension_interfaces (CN4.10 CN6.11 R22.1), mcu (U1.71)
PB9: arduino_extension_interfaces (CN4.9 CN6.13 R23.1), mcu (U1.72)
PB10: arduino_extension_interfaces (R20.2), mcu (U1.38)
PB11: arduino_extension_interfaces (R21.2), mcu (U1.39)
PB12: arduino_extension_interfaces (CN6.38), mcu (U1.40)
PB13: arduino_extension_interfaces (CN6.36), mcu (U1.41)
PB14: arduino_extension_interfaces (CN5.7 CN6.33), mcu (U1.42)
PB15: arduino_extension_interfaces (CN6.34), mcu (U1.43)
PC0: arduino_extension_interfaces (CN6.20), mcu (U1.17)
PC1: arduino_extension_interfaces (CN6.22), mcu (U1.18)
PC2: arduino_extension_interfaces (CN1.43), mcu (U1.19)
PC3: arduino_extension_interfaces (CN6.24), mcu (U1.23)
PC4: arduino_extension_interfaces (CN6.26), mcu (U1.24)
PC5: arduino_extension_interfaces (CN1.45), mcu (U1.25)
PC6: arduino_extension_interfaces (CN6.12), mcu (U1.26)
PC7: arduino_extension_interfaces (CN6.14), mcu (U1.46)
PC8: arduino_extension_interfaces (CN6.10), mcu (U1.47)
PC9: arduino_extension_interfaces (CN6.9), mcu (JP1.1 U1.62)
PC10: arduino_extension_interfaces (CN1.11), mcu (U1.64)
PC11: arduino_extension_interfaces (CN1.12), mcu (U1.65)
PC12: arduino_extension_interfaces (CN1.9), mcu (U1.5)
PC13: arduino_extension_interfaces (CN1.31), mcu (R6.1 U1.6)
PC14: arduino_extension_interfaces (R17.2), mcu (R7.1 U1.7)
PC15: arduino_extension_interfaces (R16.2), mcu (R8.1 U1.8)
PD0: arduino_extension_interfaces (CN1.21), mcu (U1.48)
PD1: arduino_extension_interfaces (CN1.19), mcu (U1.49)
PD2: arduino_extension_interfaces (CN1.10), mcu (U1.75)
PD3: arduino_extension_interfaces (CN1.23), mcu (U1.76)
PD4: arduino_extension_interfaces (CN1.25), mcu (U1.77)
PD5: arduino_extension_interfaces (CN1.34), mcu (U1.78)
PD6: arduino_extension_interfaces (CN1.5), mcu (U1.1)
PD7: arduino_extension_interfaces (CN1.6), mcu (U1.2)
PD8: arduino_extension_interfaces (CN1.7), mcu (U1.3)
PD9: arduino_extension_interfaces (CN1.8), mcu (U1.4)
PD10: arduino_extension_interfaces (CN6.5), mcu (U1.34)
PD11: arduino_extension_interfaces (CN6.6), mcu (U1.35)
PD12: arduino_extension_interfaces (CN6.7), mcu (U1.36)
PD13: arduino_extension_interfaces (CN6.8), mcu (U1.37)
PD14: arduino_extension_interfaces (CN6.3), mcu (U1.56)
PD15: arduino_extension_interfaces (CN6.4), mcu (U1.57)
PE0: arduino_extension_interfaces (CN6.1), mcu (U1.58)
PE1: arduino_extension_interfaces (CN6.2), mcu (U1.59)
PE2: arduino_extension_interfaces (CN1.1), mcu (U1.73)
PE3: arduino_extension_interfaces (CN1.2), mcu (U1.74)
PE4: arduino_extension_interfaces (CN1.3), mcu (U1.79)
PE5: arduino_extension_interfaces (CN1.4), mcu (U1.80)
PF0: arduino_extension_interfaces (R19.2), mcu (R9.2 U1.15)
PF1: arduino_extension_interfaces (R18.2), mcu (R10.2 U1.16)

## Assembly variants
None: all parts fitted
